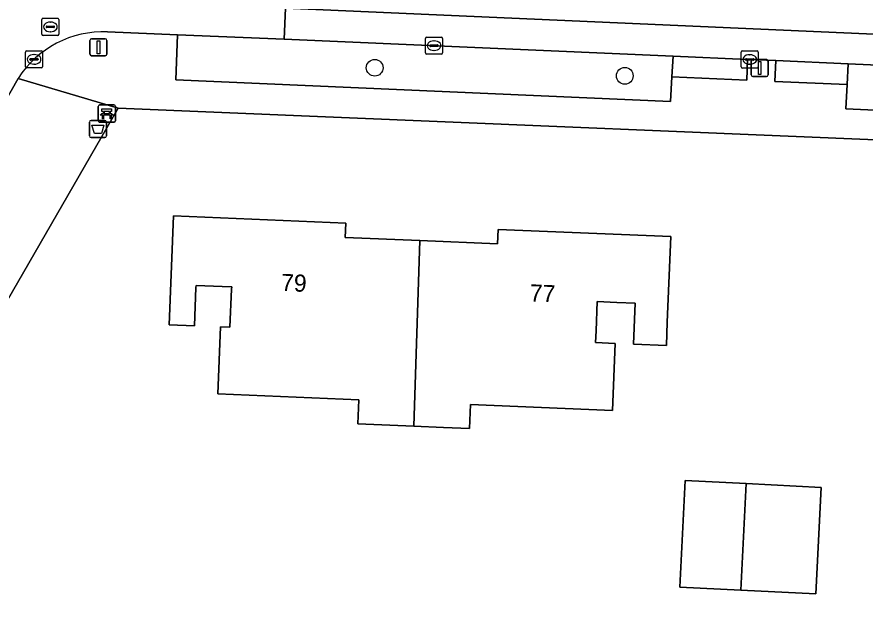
# Model space of a CAD drawing. Extents: x 161772 to 163126, y 383092 to 383917.
# Drawn here: x 162436.35 to 162485.86, y 383616.17 to 383650.31 of the extents above; entities that cross this region are included whole.
import ezdxf

# ---------------------------------------------------------------- set-up
doc = ezdxf.new("R2010")
doc.units = 0
for name, color, linetype in [('IMGEO_Afvalbak', 7, 'Continuous'), ('IMGEO_Bank', 7, 'Continuous'), ('IMGEO_Boom', 7, 'Continuous'), ('IMGEO_Erf', 7, 'Continuous'), ('IMGEO_Groenvoorziening', 7, 'Continuous'), ('IMGEO_Kolk', 7, 'Continuous'), ('IMGEO_Lichtmast', 7, 'Continuous'), ('IMGEO_Pand', 7, 'Continuous'), ('IMGEO_Pand_nummerreeks', 7, 'Continuous'), ('IMGEO_Rijbaan_lokaal_gesloten', 7, 'Continuous'), ('IMGEO_Rijbaan_lokaal_open', 7, 'Continuous'), ('IMGEO_Rioolput', 7, 'Continuous'), ('IMGEO_Voetpad_open', 7, 'Continuous')]:
    doc.layers.add(name, color=color, linetype=linetype)

msp = doc.modelspace()

# ---------------------------------------------------------------- linework, layer by layer
at = {"layer": 'IMGEO_Afvalbak'}
for p, q in [((162440.58, 383643.373), (162440.58, 383644.173)), ((162440.58, 383644.173), (162440.58, 383643.373)), ((162440.68, 383644.273), (162441.47, 383644.273)), ((162441.47, 383644.273), (162440.68, 383644.273)), ((162441.57, 383644.173), (162441.57, 383643.373)), ((162441.57, 383643.373), (162441.57, 383644.173)), ((162441.47, 383643.273), (162440.68, 383643.273)), ((162440.68, 383643.273), (162441.47, 383643.273))]:
    msp.add_line(p, q, dxfattribs=at)
msp.add_lwpolyline([(162440.723, 383643.987), (162441.427, 383643.987), (162441.278, 383643.517), (162440.872, 383643.517), (162440.723, 383643.987)], dxfattribs=at)
for centre, start, end in [((162440.68, 383644.173), 90, 180), ((162440.68, 383644.173), 90, 180), ((162441.47, 383644.173), 0, 90), ((162441.47, 383644.173), 360, 90), ((162440.68, 383643.373), 180, 270), ((162440.68, 383643.373), 180, 270), ((162441.47, 383643.373), 270, 0), ((162441.47, 383643.373), 270, 0)]:
    msp.add_arc(centre, 0.1, start, end, dxfattribs=at)
at = {"layer": 'IMGEO_Bank'}
for p, q in [((162441.095, 383644.247), (162441.095, 383645.088)), ((162441.095, 383645.088), (162441.095, 383644.247)), ((162441.17, 383645.172), (162442.011, 383645.172)), ((162442.011, 383645.172), (162441.17, 383645.172)), ((162442.095, 383645.097), (162442.095, 383644.256)), ((162442.095, 383644.256), (162442.095, 383645.097)), ((162441.792, 383644.57), (162441.399, 383644.57)), ((162441.404, 383644.678), (162441.404, 383644.784)), ((162441.448, 383644.784), (162441.448, 383644.678)), ((162441.736, 383644.79), (162441.454, 383644.79)), ((162441.454, 383644.672), (162441.736, 383644.672)), ((162441.742, 383644.678), (162441.742, 383644.784)), ((162441.786, 383644.784), (162441.786, 383644.678)), ((162442.02, 383644.172), (162441.179, 383644.172)), ((162441.179, 383644.172), (162442.02, 383644.172))]:
    msp.add_line(p, q, dxfattribs=at)
for points in [[(162441.398, 383644.79), (162441.312, 383644.79), (162441.312, 383644.951), (162441.875, 383644.951), (162441.875, 383644.79), (162441.792, 383644.79)], [(162441.342, 383644.57), (162441.2, 383644.57), (162441.312, 383644.672), (162441.398, 383644.672)], [(162441.392, 383644.563), (162441.392, 383644.356), (162441.349, 383644.356), (162441.349, 383644.563)], [(162441.792, 383644.672), (162441.875, 383644.672), (162441.987, 383644.57), (162441.848, 383644.57)], [(162441.842, 383644.563), (162441.842, 383644.356), (162441.798, 383644.356), (162441.798, 383644.563)]]:
    msp.add_lwpolyline(points, dxfattribs=at)
for centre, radius, start, end in [((162441.173, 383645.094), 0.0779, 92.4484, 184.2845), ((162441.173, 383645.094), 0.0779, 92.4484, 184.2845), ((162442.017, 383645.094), 0.0779, 2.4484, 94.2845), ((162442.017, 383645.094), 0.0779, 2.4484, 94.2845), ((162441.342, 383644.563), 0.00671, 2.8957, 87.1043), ((162441.399, 383644.563), 0.00671, 92.8957, 177.1043), ((162441.397, 383644.783), 0.00671, 2.8957, 87.1043), ((162441.397, 383644.679), 0.00671, 272.8957, 357.1043), ((162441.454, 383644.783), 0.00671, 92.8957, 177.1043), ((162441.454, 383644.679), 0.00671, 182.8957, 267.1043), ((162441.736, 383644.783), 0.00671, 2.8957, 87.1043), ((162441.736, 383644.679), 0.00671, 272.8957, 357.1043), ((162441.793, 383644.783), 0.00671, 92.8957, 177.1043), ((162441.793, 383644.679), 0.00671, 182.8957, 267.1043), ((162441.791, 383644.563), 0.00671, 2.8957, 87.1043), ((162441.848, 383644.563), 0.00671, 92.8957, 177.1043), ((162441.173, 383644.25), 0.0779, 182.4484, 274.2845), ((162441.173, 383644.25), 0.0779, 182.4484, 274.2845), ((162442.017, 383644.25), 0.0779, 272.4484, 4.2845), ((162442.017, 383644.25), 0.0779, 272.4484, 4.2845)]:
    msp.add_arc(centre, radius, start, end, dxfattribs=at)
at = {"layer": 'IMGEO_Boom'}
for centre in [(162457.233, 383647.345), (162471.833, 383646.873)]:
    msp.add_circle(centre, 0.489, dxfattribs=at)
at = {"layer": 'IMGEO_Erf'}
msp.add_lwpolyline([(162462.704, 383536.779), (162483.744, 383554.98), (162500, 383574.599), (162526.947, 383607.122), (162543.804, 383623.317), (162548.918, 383628.126), (162539.791, 383641.093), (162527.133, 383641.683), (162527.105, 383641.456), (162500, 383642.583), (162442.25, 383644.984), (162375.184, 383528.714), (162418.191, 383500), (162425.357, 383495.215)], dxfattribs=at)
for points in [[(162448.068, 383628.314), (162448.231, 383632.23), (162448.784, 383632.207), (162448.877, 383634.436), (162448.89, 383634.554), (162448.329, 383634.578), (162446.805, 383634.642), (162446.8, 383634.523), (162446.707, 383632.293), (162445.228, 383632.355), (162445.494, 383638.709), (162455.544, 383638.286), (162455.508, 383637.45), (162459.863, 383637.267), (162464.402, 383637.076), (162464.438, 383637.917), (162474.527, 383637.492), (162474.316, 383632.497), (162474.259, 383631.135), (162472.34, 383631.215), (162472.44, 383633.614), (162471.378, 383633.658), (162470.229, 383633.706), (162470.158, 383632.003), (162470.129, 383631.306), (162471.279, 383631.259), (162471.115, 383627.342), (162462.822, 383627.689), (162462.763, 383626.29), (162461.244, 383626.353), (162459.509, 383626.426), (162456.248, 383626.562), (162456.306, 383627.97)], [(162478.603, 383616.867), (162475.047, 383617.049), (162475.36, 383623.269), (162478.916, 383623.087), (162483.295, 383622.863), (162482.982, 383616.643)]]:
    msp.add_lwpolyline(points, close=True, dxfattribs=at)
at = {"layer": 'IMGEO_Groenvoorziening'}
msp.add_lwpolyline([(162474.662, 383648.021), (162451.954, 383649.018), (162445.718, 383649.273), (162445.618, 383646.635), (162474.51, 383645.371), (162474.586, 383646.815)], close=True, dxfattribs=at)
msp.add_lwpolyline([(162489.397, 383647.276), (162488.786, 383647.405), (162484.88, 383647.576), (162484.818, 383646.366), (162484.744, 383644.956), (162492.009, 383644.621), (162492.044, 383645.274)], dxfattribs=at)
at = {"layer": 'IMGEO_Kolk'}
for p, q in [((162460.195, 383648.208), (162460.195, 383649.06)), ((162460.27, 383649.134), (162461.122, 383649.134)), ((162460.683, 383648.914), (162460.708, 383648.914)), ((162461.196, 383649.06), (162461.196, 383648.208)), ((162460.454, 383648.628), (162460.454, 383648.64)), ((162460.892, 383648.591), (162460.494, 383648.591)), ((162460.497, 383648.677), (162460.895, 383648.677)), ((162460.938, 383648.64), (162460.938, 383648.628)), ((162461.122, 383648.134), (162460.27, 383648.134)), ((162460.706, 383648.354), (162460.681, 383648.354)), ((162478.628, 383647.401), (162478.628, 383648.253)), ((162478.703, 383648.327), (162479.555, 383648.327)), ((162479.116, 383648.107), (162479.141, 383648.107)), ((162479.629, 383648.253), (162479.629, 383647.401)), ((162478.887, 383647.821), (162478.887, 383647.833)), ((162479.325, 383647.784), (162478.927, 383647.784)), ((162478.93, 383647.87), (162479.328, 383647.87)), ((162479.139, 383647.547), (162479.114, 383647.547)), ((162479.371, 383647.833), (162479.371, 383647.821)), ((162479.555, 383647.327), (162478.703, 383647.327))]:
    msp.add_line(p, q, dxfattribs=at)
for points in [[(162460.195, 383648.208), (162460.195, 383649.06)], [(162460.27, 383649.134), (162461.122, 383649.134)], [(162461.196, 383649.06), (162461.196, 383648.208)], [(162461.122, 383648.134), (162460.27, 383648.134)], [(162478.628, 383647.401), (162478.628, 383648.253)], [(162478.703, 383648.327), (162479.555, 383648.327)], [(162479.629, 383648.253), (162479.629, 383647.401)], [(162479.555, 383647.327), (162478.703, 383647.327)]]:
    msp.add_lwpolyline(points, dxfattribs=at)
for centre, radius, start, end in [((162460.272, 383649.058), 0.0765, 91.552, 178.448), ((162460.272, 383649.058), 0.0765, 91.552, 178.448), ((162461.12, 383649.058), 0.0765, 1.552, 88.448), ((162461.12, 383649.058), 0.0765, 1.552, 88.448), ((162460.494, 383648.637), 0.0403, 85.8775, 175.7526), ((162460.491, 383648.627), 0.0366, 178.938, 274.7102), ((162460.895, 383648.634), 0.043, 264.8664, 352.4533), ((162460.899, 383648.639), 0.0386, 1.7309, 96.639), ((162460.272, 383648.21), 0.0765, 181.552, 268.448), ((162460.272, 383648.21), 0.0765, 181.552, 268.448), ((162461.12, 383648.21), 0.0765, 271.552, 358.448), ((162461.12, 383648.21), 0.0765, 271.552, 358.448), ((162478.705, 383648.251), 0.0765, 91.552, 178.448), ((162478.705, 383648.251), 0.0765, 91.552, 178.448), ((162479.553, 383648.251), 0.0765, 1.552, 88.448), ((162479.553, 383648.251), 0.0765, 1.552, 88.448), ((162478.927, 383647.83), 0.0403, 85.8775, 175.7526), ((162478.924, 383647.82), 0.0366, 178.938, 274.7102), ((162479.328, 383647.827), 0.043, 264.8664, 352.4533), ((162479.332, 383647.832), 0.0386, 1.7309, 96.639), ((162478.705, 383647.403), 0.0765, 181.552, 268.448), ((162478.705, 383647.403), 0.0765, 181.552, 268.448), ((162479.553, 383647.403), 0.0765, 271.552, 358.448), ((162479.553, 383647.403), 0.0765, 271.552, 358.448)]:
    msp.add_arc(centre, radius, start, end, dxfattribs=at)
for centre, major_axis, ratio, start_param, end_param in [((162460.682, 383648.634), (-0.387, 0.002), 0.722429, 4.712389, 7.853982), ((162460.707, 383648.634), (-0.39, 0.002), 0.717154, 1.570796, 4.712389), ((162479.115, 383647.827), (-0.387, 0.002), 0.722429, 4.712389, 7.853982), ((162479.14, 383647.827), (-0.39, 0.002), 0.717154, 1.570796, 4.712389)]:
    msp.add_ellipse(centre, major_axis=major_axis, ratio=ratio, start_param=start_param, end_param=end_param, dxfattribs=at)
at = {"layer": 'IMGEO_Lichtmast'}
for p, q in [((162440.607, 383648.14), (162440.607, 383648.94)), ((162440.607, 383648.94), (162440.607, 383648.14)), ((162440.707, 383649.04), (162441.497, 383649.04)), ((162441.497, 383649.04), (162440.707, 383649.04)), ((162441.597, 383648.94), (162441.597, 383648.14)), ((162441.597, 383648.14), (162441.597, 383648.94)), ((162441.497, 383648.04), (162440.707, 383648.04)), ((162440.707, 383648.04), (162441.497, 383648.04)), ((162479.212, 383646.925), (162479.212, 383647.725)), ((162479.212, 383647.725), (162479.212, 383646.925)), ((162479.312, 383647.825), (162480.102, 383647.825)), ((162480.102, 383647.825), (162479.312, 383647.825)), ((162480.202, 383647.725), (162480.202, 383646.925)), ((162480.202, 383646.925), (162480.202, 383647.725)), ((162480.102, 383646.825), (162479.312, 383646.825)), ((162479.312, 383646.825), (162480.102, 383646.825))]:
    msp.add_line(p, q, dxfattribs=at)
for points in [[(162441.027, 383648.915), (162441.177, 383648.915), (162441.177, 383648.165), (162441.027, 383648.165), (162441.027, 383648.915)], [(162479.632, 383647.7), (162479.782, 383647.7), (162479.782, 383646.95), (162479.632, 383646.95), (162479.632, 383647.7)]]:
    msp.add_lwpolyline(points, dxfattribs=at)
for centre, start, end in [((162440.707, 383648.94), 90, 180), ((162440.707, 383648.94), 90, 180), ((162441.497, 383648.94), 0, 90), ((162441.497, 383648.94), 360, 90), ((162440.707, 383648.14), 180, 270), ((162440.707, 383648.14), 180, 270), ((162441.497, 383648.14), 270, 0), ((162441.497, 383648.14), 270, 0), ((162479.312, 383647.725), 90, 180), ((162479.312, 383647.725), 90, 180), ((162480.102, 383647.725), 0, 90), ((162480.102, 383647.725), 360, 90), ((162479.312, 383646.925), 180, 270), ((162479.312, 383646.925), 180, 270), ((162480.102, 383646.925), 270, 0), ((162480.102, 383646.925), 270, 0)]:
    msp.add_arc(centre, 0.1, start, end, dxfattribs=at)
at = {"layer": 'IMGEO_Pand'}
for points in [[(162459.863, 383637.267), (162455.508, 383637.45), (162455.544, 383638.286), (162445.494, 383638.709), (162445.228, 383632.355), (162446.707, 383632.293), (162446.8, 383634.523), (162446.805, 383634.642), (162448.329, 383634.578), (162448.89, 383634.554), (162448.877, 383634.436), (162448.784, 383632.207), (162448.231, 383632.23), (162448.068, 383628.314), (162456.306, 383627.97), (162456.248, 383626.562), (162459.509, 383626.426)], [(162474.259, 383631.135), (162474.316, 383632.497), (162474.527, 383637.492), (162464.438, 383637.917), (162464.402, 383637.076), (162459.863, 383637.267), (162459.509, 383626.426), (162461.244, 383626.353), (162462.763, 383626.29), (162462.822, 383627.689), (162471.115, 383627.342), (162471.279, 383631.259), (162470.129, 383631.306), (162470.158, 383632.003), (162470.229, 383633.706), (162471.378, 383633.658), (162472.44, 383633.614), (162472.34, 383631.215)], [(162478.603, 383616.867), (162478.916, 383623.087), (162475.36, 383623.269), (162475.047, 383617.049)], [(162478.603, 383616.867), (162482.982, 383616.643), (162483.295, 383622.863), (162478.916, 383623.087)]]:
    msp.add_lwpolyline(points, close=True, dxfattribs=at)
at = {"layer": 'IMGEO_Rijbaan_lokaal_gesloten'}
msp.add_lwpolyline([(162523.65, 383645.863), (162528.021, 383645.714), (162546.24, 383644.939), (162546.283, 383646.661), (162452.027, 383650.822), (162451.954, 383649.018), (162474.662, 383648.021), (162479.006, 383647.832), (162480.659, 383647.76), (162484.88, 383647.576), (162488.786, 383647.405), (162518.458, 383646.119)], close=True, dxfattribs=at)
at = {"layer": 'IMGEO_Rijbaan_lokaal_open'}
for points in [[(162441.626, 383649.441), (162445.718, 383649.273), (162451.954, 383649.018), (162452.027, 383650.822), (162452.209, 383653.79)], [(162452.209, 383653.79), (162452.027, 383650.822), (162546.283, 383646.661), (162546.24, 383644.939), (162548.214, 383644.855), (162566.564, 383643.453), (162571.364, 383644.272), (162571.215, 383646.047)], [(162429.004, 383641.083), (162428.716, 383640.58), (162431.847, 383638.777), (162434.773, 383643.833), (162436.417, 383646.724)]]:
    msp.add_lwpolyline(points, dxfattribs=at)
msp.add_arc((162441.408, 383643.508), 5.937, 87.8928, 147.2, dxfattribs=at)
at = {"layer": 'IMGEO_Rioolput'}
for p, q in [((162437.798, 383649.302), (162437.798, 383650.154)), ((162437.873, 383650.228), (162438.725, 383650.228)), ((162438.286, 383650.008), (162438.311, 383650.008)), ((162438.799, 383650.154), (162438.799, 383649.302)), ((162438.057, 383649.722), (162438.057, 383649.734)), ((162438.495, 383649.685), (162438.097, 383649.685)), ((162438.1, 383649.771), (162438.498, 383649.771)), ((162438.309, 383649.448), (162438.284, 383649.448)), ((162438.541, 383649.734), (162438.541, 383649.722)), ((162438.725, 383649.228), (162437.873, 383649.228)), ((162436.844, 383647.407), (162436.844, 383648.259)), ((162436.919, 383648.333), (162437.771, 383648.333)), ((162437.332, 383648.113), (162437.357, 383648.113)), ((162437.845, 383648.259), (162437.845, 383647.407)), ((162437.103, 383647.827), (162437.103, 383647.839)), ((162437.541, 383647.79), (162437.143, 383647.79)), ((162437.146, 383647.876), (162437.544, 383647.876)), ((162437.355, 383647.553), (162437.33, 383647.553)), ((162437.587, 383647.839), (162437.587, 383647.827)), ((162437.771, 383647.333), (162436.919, 383647.333))]:
    msp.add_line(p, q, dxfattribs=at)
for points in [[(162437.798, 383649.302), (162437.798, 383650.154)], [(162437.873, 383650.228), (162438.725, 383650.228)], [(162438.799, 383650.154), (162438.799, 383649.302)], [(162438.725, 383649.228), (162437.873, 383649.228)], [(162436.844, 383647.407), (162436.844, 383648.259)], [(162436.919, 383648.333), (162437.771, 383648.333)], [(162437.845, 383648.259), (162437.845, 383647.407)], [(162437.771, 383647.333), (162436.919, 383647.333)]]:
    msp.add_lwpolyline(points, dxfattribs=at)
for centre, radius, start, end in [((162437.875, 383650.152), 0.0765, 91.552, 178.448), ((162437.875, 383650.152), 0.0765, 91.552, 178.448), ((162438.723, 383650.152), 0.0765, 1.552, 88.448), ((162438.723, 383650.152), 0.0765, 1.552, 88.448), ((162438.097, 383649.731), 0.0403, 85.8775, 175.7526), ((162438.094, 383649.721), 0.0366, 178.938, 274.7102), ((162438.498, 383649.728), 0.043, 264.8664, 352.4533), ((162438.502, 383649.733), 0.0386, 1.7309, 96.639), ((162437.875, 383649.304), 0.0765, 181.552, 268.448), ((162437.875, 383649.304), 0.0765, 181.552, 268.448), ((162438.723, 383649.304), 0.0765, 271.552, 358.448), ((162438.723, 383649.304), 0.0765, 271.552, 358.448), ((162436.921, 383648.257), 0.0765, 91.552, 178.448), ((162436.921, 383648.257), 0.0765, 91.552, 178.448), ((162437.769, 383648.257), 0.0765, 1.552, 88.448), ((162437.769, 383648.257), 0.0765, 1.552, 88.448), ((162436.921, 383647.409), 0.0765, 181.552, 268.448), ((162436.921, 383647.409), 0.0765, 181.552, 268.448), ((162437.143, 383647.836), 0.0403, 85.8775, 175.7526), ((162437.14, 383647.826), 0.0366, 178.938, 274.7102), ((162437.544, 383647.833), 0.043, 264.8664, 352.4533), ((162437.548, 383647.838), 0.0386, 1.7309, 96.639), ((162437.769, 383647.409), 0.0765, 271.552, 358.448), ((162437.769, 383647.409), 0.0765, 271.552, 358.448)]:
    msp.add_arc(centre, radius, start, end, dxfattribs=at)
for centre, major_axis, ratio, start_param, end_param in [((162438.285, 383649.728), (-0.387, 0.002), 0.722429, 4.712389, 7.853982), ((162438.31, 383649.728), (-0.39, 0.002), 0.717154, 1.570796, 4.712389), ((162437.331, 383647.833), (-0.387, 0.002), 0.722429, 4.712389, 7.853982), ((162437.356, 383647.833), (-0.39, 0.002), 0.717154, 1.570796, 4.712389)]:
    msp.add_ellipse(centre, major_axis=major_axis, ratio=ratio, start_param=start_param, end_param=end_param, dxfattribs=at)
at = {"layer": 'IMGEO_Voetpad_open'}
for points in [[(162548.214, 383644.855), (162546.24, 383644.939), (162528.021, 383645.714), (162527.973, 383644.496), (162523.601, 383644.684), (162523.544, 383643.326), (162515.076, 383643.701), (162515.06, 383644.262), (162492.044, 383645.274), (162492.009, 383644.621), (162484.744, 383644.956), (162484.818, 383646.366), (162480.603, 383646.538), (162480.659, 383647.76), (162479.006, 383647.832), (162478.95, 383646.613), (162474.586, 383646.815), (162474.51, 383645.371), (162445.618, 383646.635), (162445.718, 383649.273), (162441.626, 383649.441)], [(162375.184, 383528.714), (162442.25, 383644.984), (162436.417, 383646.724), (162434.773, 383643.833)], [(162436.417, 383646.724), (162442.25, 383644.984), (162500, 383642.583), (162527.105, 383641.456), (162527.133, 383641.683), (162539.791, 383641.093), (162542.432, 383640.97), (162553.59, 383641.251)]]:
    msp.add_lwpolyline(points, dxfattribs=at)
for points in [[(162474.586, 383646.815), (162478.95, 383646.613), (162479.006, 383647.832), (162474.662, 383648.021)], [(162484.88, 383647.576), (162480.659, 383647.76), (162480.603, 383646.538), (162484.818, 383646.366)]]:
    msp.add_lwpolyline(points, close=True, dxfattribs=at)
msp.add_arc((162441.408, 383643.508), 5.937, 87.8928, 147.2, dxfattribs=at)

# ---------------------------------------------------------------- texts
at = {"layer": 'IMGEO_Pand_nummerreeks'}
for s, p in [('79', (162451.753, 383634.325)), ('77', (162466.27, 383633.714))]:
    msp.add_text(s, height=1, rotation=357.5936, dxfattribs=at).set_placement(p)

doc.saveas('drawing.dxf')
